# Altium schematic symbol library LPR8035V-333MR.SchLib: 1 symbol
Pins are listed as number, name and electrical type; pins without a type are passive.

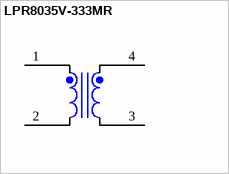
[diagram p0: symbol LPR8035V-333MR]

## LPR8035V-333MR
designator L?, comment 33uH
Coupled inductor, 33 µH, 0.75 A, 0.2 ohm, SMD; Manufacturer: Coilcraft; PartNumber: LPR8035V-333MR; SymbolVersion: use current date i.e. 2008-05-20; SymbolCreator: Use a-id; U/M: EA, IN, or GM
footprint LPR8035V-223x (SMD, 4-Leads, Body 7.92x6.4mm)
pins: 1, 2, 3, 4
